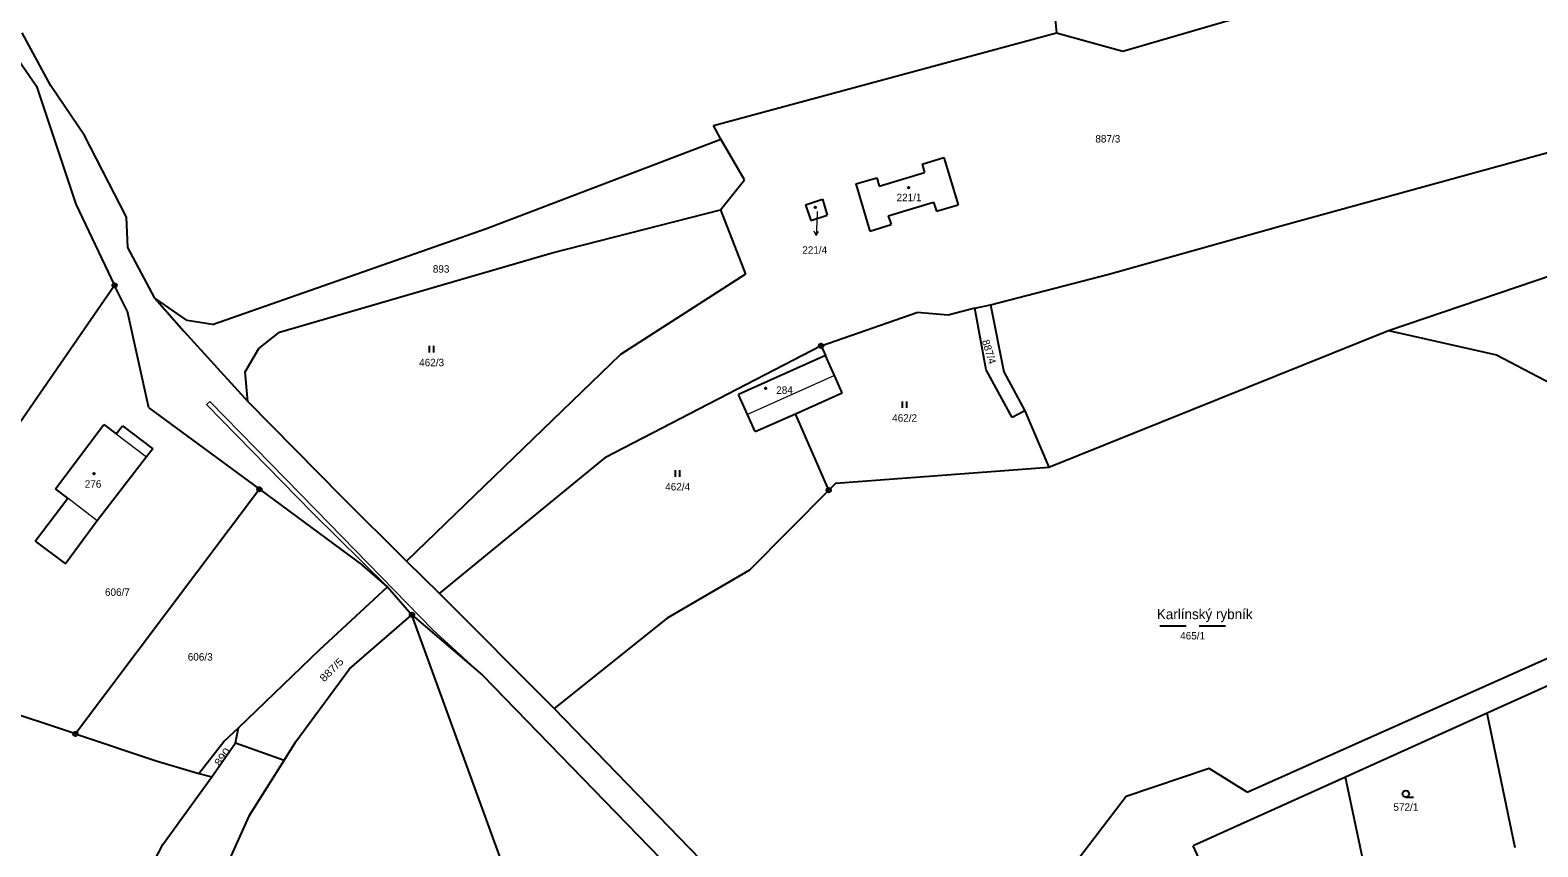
# Model space of a CAD drawing. Extents: x -739410 to -735662, y -942282 to -940043.
# Drawn here: x -737598.7 to -737254.3, y -941768.5 to -941581.8 of the extents above; entities that cross this region are included whole.
import ezdxf
from ezdxf.enums import TextEntityAlignment as Align

# ---------------------------------------------------------------- set-up
doc = ezdxf.new("R2010")
doc.units = 0
doc.header["$LTSCALE"] = 0.68
for name, color, linetype, lineweight in [('1', 7, 'Continuous', 25), ('13', 7, 'Continuous', 13), ('3', 7, 'Continuous', 25), ('4', 7, 'Continuous', 13), ('5', 7, 'Continuous', 25), ('7', 7, 'Continuous', 13), ('8', 7, 'Continuous', 25)]:
    doc.layers.add(name, color=color, linetype=linetype, lineweight=lineweight)
doc.layers.add('2', color=7, linetype='Continuous')

msp = doc.modelspace()

# ---------------------------------------------------------------- linework, layer by layer
at = {"layer": '1'}
for p, q in [((-737349.15, -941586.68), (-737274.72, -941564.87)), ((-737365.57, -941569.02), (-737364.27, -941582.48)), ((-737593.94, -941594.6), (-737600.52, -941582.46)), ((-737442.6, -941603.6), (-737364.27, -941582.48)), ((-737364.27, -941582.48), (-737349.15, -941586.68)), ((-737601.39, -941588.51), (-737597.24, -941594.67)), ((-737597.24, -941594.67), (-737588.25, -941621.64)), ((-737586.25, -941605.9), (-737593.94, -941594.6)), ((-737271.44, -941615.13), (-737218.78, -941600.71)), ((-737576.69, -941624.57), (-737586.25, -941605.9)), ((-737440.9, -941606.78), (-737442.6, -941603.6)), ((-737494.42, -941627.16), (-737440.9, -941606.78)), ((-737435.55, -941616.08), (-737440.9, -941606.78)), ((-737394.96, -941612.44), (-737390, -941610.94)), ((-737394.96, -941612.44), (-737394.39, -941614.35)), ((-737390, -941610.94), (-737386.72, -941621.76)), ((-737441.01, -941622.88), (-737435.55, -941616.08)), ((-737410.11, -941616.99), (-737405.33, -941615.57)), ((-737405.33, -941615.57), (-737404.76, -941617.48)), ((-737404.76, -941617.48), (-737394.39, -941614.35)), ((-737311.86, -941626.28), (-737271.44, -941615.13)), ((-737288.45, -941650.5), (-737186.48, -941615.88)), ((-737410.11, -941616.99), (-737406.88, -941627.78)), ((-737588.25, -941621.64), (-737579.37, -941640.18)), ((-737479.42, -941632.74), (-737441.01, -941622.88)), ((-737441.01, -941622.88), (-737435.27, -941637.63)), ((-737421.57, -941621.73), (-737417.68, -941620.5)), ((-737421.57, -941621.73), (-737420.37, -941625.31)), ((-737417.68, -941620.5), (-737416.63, -941624.11)), ((-737402.73, -941624.28), (-737392.35, -941621.15)), ((-737392.35, -941621.15), (-737391.67, -941623.2)), ((-737391.67, -941623.2), (-737386.72, -941621.76)), ((-737576.35, -941631.53), (-737576.69, -941624.57)), ((-737420.37, -941625.31), (-737416.63, -941624.11)), ((-737406.88, -941627.78), (-737402.03, -941626.23)), ((-737402.73, -941624.28), (-737402.03, -941626.23)), ((-737352.28, -941637.64), (-737311.86, -941626.28)), ((-737557.05, -941649.14), (-737494.42, -941627.16)), ((-737570.22, -941643.11), (-737576.35, -941631.53)), ((-737541.72, -941650.86), (-737479.42, -941632.74)), ((-737579.37, -941640.18), (-737637.99, -941725.15)), ((-737576.47, -941646.17), (-737579.37, -941640.18)), ((-737435.27, -941637.63), (-737463.81, -941655.97)), ((-737379.37, -941644.64), (-737352.28, -941637.64)), ((-737570.22, -941643.11), (-737563.58, -941650.66)), ((-737562.84, -941648.24), (-737570.22, -941643.11)), ((-737571.58, -941668.17), (-737576.47, -941646.17)), ((-737418.04, -941653.99), (-737396.18, -941646.41)), ((-737389.04, -941646.96), (-737396.18, -941646.41)), ((-737382.9, -941645.39), (-737389.04, -941646.96)), ((-737382.9, -941645.39), (-737379.37, -941644.64)), ((-737380.36, -941659.46), (-737382.9, -941645.39)), ((-737379.37, -941644.64), (-737376.32, -941659.9)), ((-737563.58, -941650.66), (-737548.92, -941666.73)), ((-737557.05, -941649.14), (-737562.84, -941648.24)), ((-737546.42, -941654.62), (-737541.72, -941650.86)), ((-737366.05, -941681.71), (-737288.45, -941650.5)), ((-737288.45, -941650.5), (-737263.75, -941656.07)), ((-737418.04, -941653.99), (-737467.27, -941679.55)), ((-737418.04, -941653.99), (-737417.05, -941656.18)), ((-737549.55, -941659.94), (-737546.42, -941654.62)), ((-737463.81, -941655.97), (-737512.69, -941703.22)), ((-737417.05, -941656.18), (-737436.91, -941665.13)), ((-737415, -941660.74), (-737417.05, -941656.18)), ((-737263.75, -941656.07), (-737235.19, -941671.07)), ((-737548.92, -941666.73), (-737549.55, -941659.94)), ((-737413.19, -941664.75), (-737415, -941660.74)), ((-737374.38, -941670.38), (-737380.36, -941659.46)), ((-737376.32, -941659.9), (-737371.53, -941668.88)), ((-737423.88, -941669.57), (-737413.19, -941664.75)), ((-737571.58, -941668.17), (-737546.31, -941686.78)), ((-737548.92, -941666.73), (-737527.53, -941688.43)), ((-737434.86, -941669.69), (-737436.91, -941665.13)), ((-737433.12, -941673.56), (-737434.86, -941669.69)), ((-737433.12, -941673.56), (-737423.88, -941669.57)), ((-737416.28, -941686.98), (-737423.88, -941669.57)), ((-737371.53, -941668.88), (-737374.38, -941670.38)), ((-737371.53, -941668.88), (-737366.05, -941681.71)), ((-737592.91, -941686.67), (-737581.84, -941671.94)), ((-737581.84, -941671.94), (-737578.99, -941674.12)), ((-737578.99, -941674.12), (-737577.58, -941672.26)), ((-737577.58, -941672.26), (-737570.63, -941677.54)), ((-737570.63, -941677.54), (-737572.07, -941679.4)), ((-737572.07, -941679.4), (-737583.34, -941693.98)), ((-737505.2, -941710.61), (-737467.27, -941679.55)), ((-737414.67, -941685.36), (-737366.05, -941681.71)), ((-737414.67, -941685.36), (-737416.28, -941686.98)), ((-737597.51, -941698.61), (-737590.09, -941688.8)), ((-737590.09, -941688.8), (-737592.91, -941686.67)), ((-737546.31, -941686.78), (-737588.31, -941742.69)), ((-737546.31, -941686.78), (-737522.66, -941704.2)), ((-737527.53, -941688.43), (-737512.69, -941703.22)), ((-737416.28, -941686.98), (-737434.36, -941705.23)), ((-737583.34, -941693.98), (-737590.59, -941703.85)), ((-737597.51, -941698.61), (-737590.59, -941703.85)), ((-737517.02, -941709.1), (-737522.66, -941704.2)), ((-737505.2, -941710.61), (-737512.69, -941703.22)), ((-737434.36, -941705.23), (-737453.17, -941716.22)), ((-737532.58, -941723.48), (-737517.02, -941709.1)), ((-737517.02, -941709.1), (-737511.46, -941715.45)), ((-737505.2, -941710.61), (-737479, -941736.89)), ((-737525.76, -941727.83), (-737511.46, -941715.45)), ((-737479.46, -941803.47), (-737511.46, -941715.45)), ((-737511.46, -941715.45), (-737495.33, -941729.23)), ((-737453.17, -941716.22), (-737479, -941736.89)), ((-737320.72, -941756), (-737239.26, -941719.6)), ((-737551.09, -941741.27), (-737532.58, -941723.48)), ((-737236.37, -941724.62), (-737265.92, -941737.97)), ((-737588.31, -941742.69), (-737628.96, -941729.13)), ((-737538.15, -941744.68), (-737525.76, -941727.83)), ((-737495.33, -941729.23), (-737434.6, -941791.87)), ((-737424.35, -941793.26), (-737479, -941736.89)), ((-737265.92, -941737.97), (-737298.24, -941752.57)), ((-737259.53, -941768.73), (-737265.92, -941737.97)), ((-737588.31, -941742.69), (-737569.85, -941748.85)), ((-737554.4, -941744.45), (-737551.09, -941741.27)), ((-737551.75, -941744.73), (-737551.09, -941741.27)), ((-737560.15, -941751.74), (-737554.4, -941744.45)), ((-737557.18, -941752.51), (-737551.75, -941744.73)), ((-737551.75, -941744.73), (-737540.65, -941748.66)), ((-737538.15, -941744.68), (-737540.65, -941748.66)), ((-737569.85, -941748.85), (-737560.15, -941751.74)), ((-737540.65, -941748.66), (-737548.69, -941761.46)), ((-737329.44, -941750.57), (-737348.36, -941757.03)), ((-737320.72, -941756), (-737329.44, -941750.57)), ((-737568.36, -941767.95), (-737557.18, -941752.51)), ((-737560.15, -941751.74), (-737557.18, -941752.51)), ((-737298.24, -941752.57), (-737333.04, -941768.29)), ((-737290.93, -941787.13), (-737298.24, -941752.57)), ((-737348.36, -941757.03), (-737396.68, -941819.96)), ((-737548.69, -941761.46), (-737554.12, -941773.52)), ((-737580.66, -941791.49), (-737568.36, -941767.95)), ((-737322.15, -941791.96), (-737333.04, -941768.29))]:
    msp.add_line(p, q, dxfattribs=at)
at = {"layer": '13'}
msp.add_lwpolyline([(-737534.17, -941692.17), (-737517.02, -941709.1), (-737511.46, -941715.45), (-737495.33, -941729.23), (-737506.65, -941718.99), (-737533.45, -941691.47), (-737557.64, -941666.72), (-737558.36, -941667.42)], close=True, dxfattribs=at)
at = {"layer": '3'}
for p, q in [((-737507.491, -941655.53), (-737507.491, -941654.03)), ((-737506.49, -941655.53), (-737506.49, -941654.03)), ((-737399.471, -941668.2), (-737399.471, -941666.7)), ((-737398.47, -941668.2), (-737398.47, -941666.7)), ((-737451.301, -941683.92), (-737451.301, -941682.42)), ((-737450.3, -941683.92), (-737450.3, -941682.42)), ((-737340.669, -941717.98), (-737334.669, -941717.98)), ((-737331.669, -941717.98), (-737325.669, -941717.98)), ((-737284.473, -941757.13), (-737282.723, -941757.13))]:
    msp.add_line(p, q, dxfattribs=at)
msp.add_circle((-737284.4729, -941756.3798), 0.75, dxfattribs=at)
at = {"layer": '4'}
for p, q in [((-737415, -941660.74), (-737434.86, -941669.69)), ((-737578.99, -941674.12), (-737572.07, -941679.4)), ((-737583.34, -941693.98), (-737590.09, -941688.8))]:
    msp.add_line(p, q, dxfattribs=at)
at = {"layer": '5'}
for centre in [(-737398.0568, -941617.8292), (-737419.3668, -941622.3192), (-737430.6968, -941663.6892), (-737584.0668, -941683.2292)]:
    msp.add_circle(centre, 0.175, dxfattribs=at)
at = {"layer": '7'}
msp.add_line((-737419.177, -941628.797), (-737418.625, -941627.823), dxfattribs=at)
msp.add_lwpolyline([(-737418.9, -941623.32), (-737419.02, -941625.8), (-737419.177, -941628.797), (-737419.625, -941627.771)], dxfattribs=at)
at = {"layer": '8'}
for centre, radius in [((-737579.37, -941640.1799), 0.5), ((-737579.37, -941640.1799), 0.0303), ((-737418.04, -941653.9899), 0.5), ((-737418.04, -941653.9899), 0.0303), ((-737546.31, -941686.7799), 0.5), ((-737546.31, -941686.7799), 0.0303), ((-737416.28, -941686.9799), 0.5), ((-737416.28, -941686.9799), 0.0303), ((-737511.46, -941715.4499), 0.5), ((-737511.46, -941715.4499), 0.0303), ((-737588.31, -941742.6899), 0.5), ((-737588.31, -941742.6899), 0.0303)]:
    msp.add_circle(centre, radius, dxfattribs=at)

# ---------------------------------------------------------------- texts
at = {"layer": '2'}
for s, p in [('887/3', (-737352.55, -941607.515)), ('221/1', (-737397.95, -941620.935)), ('893', (-737504.809, -941637.265)), ('462/3', (-737506.98, -941658.655)), ('284', (-737426.379, -941664.965)), ('462/2', (-737398.96, -941671.325)), ('276', (-737584.299, -941686.425)), ('462/4', (-737450.79, -941687.045)), ('606/7', (-737578.74, -941711.135)), ('465/1', (-737333.18, -941721.105)), ('606/3', (-737559.83, -941725.935)), ('572/1', (-737284.48, -941760.255))]:
    msp.add_text(s, height=1.7, dxfattribs=at).set_placement(p, align=Align.CENTER)
msp.add_text('221/4', height=1.7, dxfattribs=at).set_placement((-737416.64, -941632.935), align=Align.RIGHT)
msp.add_text('887/4', height=1.7, rotation=287, dxfattribs=at).set_placement((-737380.4772, -941655.5905), align=Align.CENTER)
at = {"layer": '2', "width": 1.15}
for s, rotation, p in [('887/5', 45, (-737529.2225, -941728.6235)), ('890', 54, (-737554.0806, -941748.4246))]:
    msp.add_text(s, height=1.7, rotation=rotation, dxfattribs=at).set_placement(p, align=Align.CENTER)
at = {"layer": '7'}
msp.add_text('Karlínský rybník', height=2.3, dxfattribs=at).set_placement((-737341.36, -941716.465))

doc.saveas('drawing.dxf')
